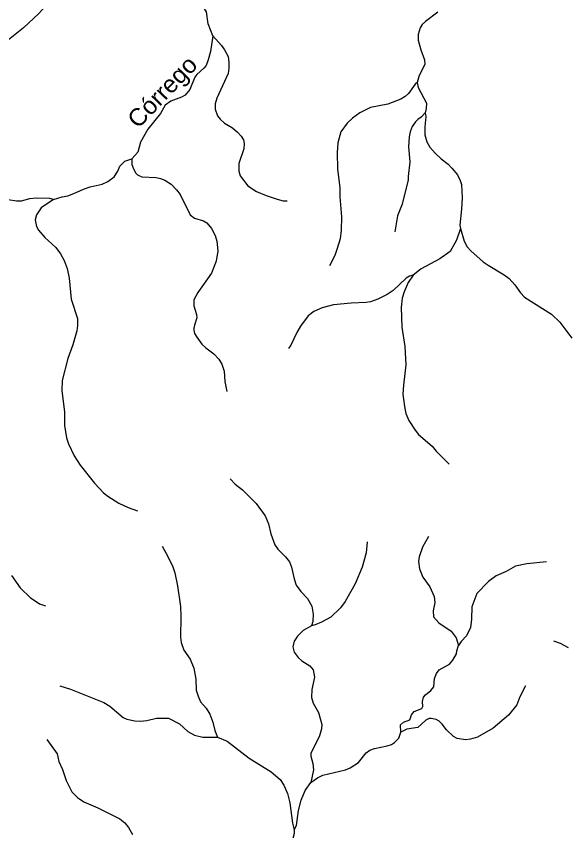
# Model space of a CAD drawing. Extents: x 320.3 to 346.3, y 7455.4 to 7483.3.
# Drawn here: x 330.97 to 333.514, y 7475.68 to 7479.448 of the extents above; entities that cross this region are included whole.
import ezdxf
from ezdxf.enums import TextEntityAlignment as Align

# ---------------------------------------------------------------- set-up
doc = ezdxf.new("R2010")
doc.units = 0
doc.header["$LTSCALE"] = 0.032
doc.layers.add('61', color=7, linetype='Continuous')
doc.layers.add('7', color=7, linetype='Continuous', lineweight=25)

msp = doc.modelspace()

# ---------------------------------------------------------------- linework, layer by layer
at = {"layer": '7'}
for points in [[(331.3345, 7479.939), (331.3321, 7479.921), (331.3062, 7479.8423), (331.267, 7479.7766), (331.2129, 7479.6574), (331.1436, 7479.5398), (331.0749, 7479.4599), (331.0041, 7479.3943), (330.8778, 7479.2962), (330.7232, 7479.1426), (330.6617, 7479.0873), (330.5618, 7479.0211), (330.529, 7479.0038), (330.4669, 7478.9821), (330.4066, 7478.9561)], [(331.8798, 7479.3576), (331.8585, 7479.4129), (331.8506, 7479.468), (331.8371, 7479.4895), (331.8191, 7479.504), (331.8043, 7479.5209), (331.7852, 7479.5696), (331.7806, 7479.589), (331.7786, 7479.6433), (331.7837, 7479.6656), (331.8182, 7479.7511), (331.8217, 7479.7725), (331.8186, 7479.8062)], [(332.9214, 7479.4663), (332.8643, 7479.4231), (332.8492, 7479.4091), (332.8398, 7479.3949), (332.8313, 7479.3626), (332.8313, 7479.3365), (332.8432, 7479.2923), (332.8606, 7479.2457), (332.8611, 7479.2246), (332.8358, 7479.1732), (332.8256, 7479.1406)], [(331.8798, 7479.3576), (331.8691, 7479.2848), (331.8582, 7479.2466), (331.8489, 7479.2196), (331.8376, 7479.2069), (331.8066, 7479.1787), (331.7966, 7479.1657), (331.7739, 7479.1091), (331.7519, 7479.0823), (331.7354, 7479.0742), (331.6855, 7479.0546), (331.6593, 7479.0358), (331.6381, 7478.9985), (331.5791, 7478.925), (331.5444, 7478.8645), (331.5322, 7478.8192), (331.5042, 7478.7888)], [(331.8798, 7479.3576), (331.9205, 7479.3129), (331.9345, 7479.2922), (331.9502, 7479.2613), (331.9544, 7479.2342), (331.9533, 7479.2075), (331.9502, 7479.1822), (331.8983, 7479.069), (331.8911, 7479.0426), (331.8903, 7479.0185), (331.9017, 7478.9878), (331.9135, 7478.9721), (331.9346, 7478.9538), (331.9705, 7478.9319), (331.9946, 7478.912), (332.0114, 7478.8928), (332.0214, 7478.8755), (332.025, 7478.8595), (332.0241, 7478.8348), (332.0004, 7478.7666), (332.0004, 7478.7314), (332.0065, 7478.7099), (332.0419, 7478.6627), (332.0825, 7478.6366), (332.1263, 7478.6178), (332.1785, 7478.601), (332.2058, 7478.594), (332.2248, 7478.5933)], [(332.8256, 7479.1406), (332.8174, 7479.1336), (332.7858, 7479.091), (332.7699, 7479.0763), (332.75, 7479.0638), (332.6906, 7479.0412), (332.6096, 7479.0262), (332.5611, 7479.0008), (332.5267, 7478.9756), (332.5015, 7478.9524), (332.473, 7478.9126), (332.4592, 7478.8619), (332.4556, 7478.8169), (332.4575, 7478.7406), (332.4685, 7478.6561), (332.4686, 7478.6125), (332.4762, 7478.5198), (332.4747, 7478.4581), (332.4695, 7478.4176), (332.4561, 7478.3732), (332.444, 7478.3408), (332.4203, 7478.2932)], [(332.8256, 7479.1406), (332.8306, 7479.118), (332.8688, 7479.0462), (332.8681, 7479.0204), (332.8626, 7479.0009)], [(332.8626, 7479.0009), (332.845, 7478.9807), (332.8291, 7478.9708), (332.8176, 7478.959), (332.8025, 7478.9374), (332.7938, 7478.9134), (332.789, 7478.8893), (332.7863, 7478.8436), (332.7927, 7478.7741), (332.7841, 7478.7067), (332.7847, 7478.691), (332.7564, 7478.5787), (332.735, 7478.5245), (332.7228, 7478.4509)], [(332.8626, 7479.0009), (332.8666, 7478.9819), (332.8612, 7478.9361), (332.8613, 7478.8993), (332.8703, 7478.8668), (332.8852, 7478.842), (332.9087, 7478.8142), (332.937, 7478.7877), (332.9699, 7478.7635), (332.9865, 7478.7454), (333.0119, 7478.7142), (333.0255, 7478.6874), (333.0307, 7478.6688), (333.0341, 7478.6077), (333.0318, 7478.555), (333.023, 7478.4806), (333.0264, 7478.4665)], [(331.1427, 7478.6005), (331.1818, 7478.6124), (331.2084, 7478.617), (331.2372, 7478.6272), (331.2813, 7478.6485), (331.3127, 7478.6588), (331.3672, 7478.671), (331.394, 7478.6826), (331.4226, 7478.7044), (331.4404, 7478.731), (331.45, 7478.7539), (331.4662, 7478.7712), (331.473, 7478.7766), (331.5042, 7478.7888)], [(331.5042, 7478.7888), (331.5053, 7478.7622), (331.5121, 7478.7412), (331.523, 7478.7211), (331.5317, 7478.7134), (331.551, 7478.7053), (331.6173, 7478.7016), (331.6383, 7478.6977), (331.6577, 7478.6901), (331.6872, 7478.6703), (331.7121, 7478.6447), (331.7282, 7478.6226), (331.7754, 7478.5287), (331.7944, 7478.5139), (331.8365, 7478.5007), (331.8526, 7478.4915), (331.8745, 7478.4651), (331.8912, 7478.4332), (331.8981, 7478.4069), (331.9037, 7478.3632), (331.8958, 7478.3155), (331.8736, 7478.2594), (331.8098, 7478.1702), (331.7921, 7478.136), (331.7917, 7478.1086), (331.8045, 7478.0687), (331.8056, 7478.0525), (331.7944, 7478.0184), (331.7914, 7478.0052), (331.7922, 7477.9955), (331.7957, 7477.9808), (331.8056, 7477.9624), (331.8289, 7477.9315), (331.8481, 7477.9139), (331.8844, 7477.8856), (331.9078, 7477.8612), (331.9218, 7477.8387), (331.9322, 7477.8052), (331.9355, 7477.7575), (331.9448, 7477.7123)], [(331.1427, 7478.6005), (331.1254, 7478.6046), (331.0642, 7478.606), (331.0313, 7478.603), (330.992, 7478.5928), (330.9705, 7478.5919), (330.8927, 7478.6045), (330.8653, 7478.6021), (330.829, 7478.5839), (330.81, 7478.5678), (330.7759, 7478.4927)], [(331.1427, 7478.6005), (331.0846, 7478.562), (331.0629, 7478.5296), (331.0574, 7478.5055), (331.0638, 7478.4749), (331.0724, 7478.4579), (331.1019, 7478.4235), (331.1538, 7478.3775), (331.1753, 7478.3494), (331.192, 7478.3177), (331.2055, 7478.2813), (331.2142, 7478.236), (331.2234, 7478.1392), (331.2527, 7478.0495), (331.2536, 7478.017), (331.2501, 7477.9918), (331.2325, 7477.9275), (331.2081, 7477.8644), (331.1826, 7477.7633), (331.1814, 7477.716), (331.1925, 7477.6157), (331.1926, 7477.5547), (331.2031, 7477.4976), (331.2123, 7477.4702), (331.2382, 7477.4141), (331.2656, 7477.3711), (331.3314, 7477.2883), (331.3741, 7477.2433), (331.3943, 7477.2271), (331.4453, 7477.1952), (331.4881, 7477.1755), (331.5313, 7477.1604)], [(333.0264, 7478.4665), (333.0083, 7478.4112), (332.9787, 7478.3597), (332.9313, 7478.3263), (332.8444, 7478.2789), (332.8068, 7478.2505)], [(333.0264, 7478.4665), (333.0431, 7478.408), (333.0576, 7478.3812), (333.0738, 7478.3618), (333.131, 7478.3122), (333.1546, 7478.2969), (333.2293, 7478.2518), (333.2516, 7478.2345), (333.2777, 7478.2045), (333.3036, 7478.1675), (333.3229, 7478.1481), (333.4475, 7478.0699), (333.4869, 7478.0319), (333.5413, 7477.9584)], [(332.8068, 7478.2505), (332.7902, 7478.2453), (332.7753, 7478.2355), (332.7148, 7478.1787), (332.6874, 7478.1606), (332.6438, 7478.1394), (332.6096, 7478.1273), (332.5895, 7478.1237), (332.52, 7478.1207), (332.438, 7478.1125), (332.3865, 7478.0985), (332.3479, 7478.0815), (332.3215, 7478.0617), (332.2854, 7478.0144), (332.2683, 7477.9851), (332.2413, 7477.9261), (332.2304, 7477.9102)], [(332.8068, 7478.2505), (332.7837, 7478.2161), (332.7655, 7478.1733), (332.7569, 7478.1433), (332.7519, 7478.1006), (332.755, 7478.0096), (332.769, 7477.9194), (332.774, 7477.8348), (332.7619, 7477.741), (332.7598, 7477.6999), (332.7668, 7477.6423), (332.7742, 7477.6102), (332.7875, 7477.5774), (332.8165, 7477.5325), (332.8328, 7477.513), (332.8948, 7477.4592), (332.9143, 7477.4353), (332.9746, 7477.376)], [(331.9609, 7477.3085), (331.9828, 7477.2833), (332.0172, 7477.2567), (332.0807, 7477.1929), (332.1216, 7477.1369), (332.1379, 7477.1001), (332.1484, 7477.0531), (332.1676, 7477.0019), (332.1811, 7476.9824), (332.2158, 7476.9471), (332.2346, 7476.9231), (332.2446, 7476.899), (332.2564, 7476.8451), (332.2663, 7476.8159), (332.2874, 7476.7859), (332.3186, 7476.7541), (332.3377, 7476.7182), (332.3443, 7476.6817), (332.3425, 7476.6479), (332.3367, 7476.6277)], [(332.8781, 7477.0413), (332.8511, 7476.991), (332.8346, 7476.9471), (332.8322, 7476.9259), (332.8372, 7476.8912), (332.8517, 7476.8533), (332.8839, 7476.8086), (332.904, 7476.7639), (332.9077, 7476.7359), (332.8999, 7476.697), (332.9016, 7476.6693), (332.9261, 7476.6418), (332.984, 7476.6027), (333.006, 7476.5729), (333.0176, 7476.5365)], [(332.5941, 7477.0156), (332.5893, 7476.9649), (332.5718, 7476.8998), (332.5389, 7476.8226), (332.4932, 7476.7399), (332.471, 7476.7106), (332.4266, 7476.6682), (332.3826, 7476.6442), (332.3541, 7476.6316), (332.3367, 7476.6277)], [(331.6447, 7476.9963), (331.6707, 7476.9516), (331.6945, 7476.9008), (331.7036, 7476.8734), (331.7165, 7476.8126), (331.7299, 7476.7177), (331.7322, 7476.671), (331.73, 7476.5756), (331.7335, 7476.5501), (331.7463, 7476.5159), (331.7755, 7476.4732), (331.7926, 7476.4319), (331.8006, 7476.3807), (331.803, 7476.3302), (331.8113, 7476.3018), (331.8228, 7476.276), (331.8489, 7476.2462), (331.8657, 7476.2184), (331.8798, 7476.182), (331.8895, 7476.1433), (331.9021, 7476.113)], [(333.4252, 7476.9231), (333.3331, 7476.9146), (333.2811, 7476.9039), (333.2376, 7476.8794), (333.1915, 7476.8584), (333.1561, 7476.8331), (333.1027, 7476.778), (333.0797, 7476.7158), (333.0781, 7476.6585), (333.073, 7476.6206), (333.0545, 7476.5814), (333.0296, 7476.5545), (333.0176, 7476.5365)], [(330.9478, 7476.8605), (330.988, 7476.8039), (331.0366, 7476.7577), (331.057, 7476.7429), (331.0779, 7476.7299), (331.1049, 7476.7195)], [(332.3367, 7476.6277), (332.298, 7476.6055), (332.2723, 7476.58), (332.2572, 7476.5575), (332.2505, 7476.5313), (332.2566, 7476.5063), (332.2747, 7476.4817), (332.2924, 7476.4662), (332.3296, 7476.4433), (332.3449, 7476.4249), (332.3502, 7476.3908), (332.3385, 7476.3338), (332.337, 7476.2964), (332.3437, 7476.2703), (332.3698, 7476.2261), (332.3839, 7476.1714), (332.383, 7476.1509), (332.3741, 7476.1189), (332.334, 7476.0366), (332.3338, 7476.0248), (332.3433, 7475.9908), (332.3463, 7475.9608), (332.3331, 7475.9029)], [(333.5272, 7476.5255), (333.4888, 7476.5464), (333.4589, 7476.557)], [(332.7497, 7476.1352), (332.7482, 7476.169), (332.7621, 7476.1817), (332.7919, 7476.1923), (332.7995, 7476.2165), (332.8114, 7476.2314), (332.8472, 7476.2457), (332.8521, 7476.2553), (332.8502, 7476.2778), (332.8558, 7476.2971), (332.8644, 7476.3085), (332.8891, 7476.3284), (332.9028, 7476.3459), (332.9065, 7476.3833), (332.9153, 7476.407), (332.9282, 7476.4244), (332.9755, 7476.4511), (332.9918, 7476.4694), (333.0085, 7476.498), (333.0096, 7476.5125), (333.0176, 7476.5365)], [(331.1709, 7476.3503), (331.2216, 7476.3352), (331.3747, 7476.2734), (331.4038, 7476.2563), (331.4648, 7476.2036), (331.4811, 7476.1953), (331.5186, 7476.1875), (331.5437, 7476.1864), (331.5749, 7476.1897), (331.6189, 7476.2006), (331.6741, 7476.2004), (331.7251, 7476.1743), (331.7642, 7476.1393), (331.7957, 7476.1213), (331.8339, 7476.1132), (331.9021, 7476.113)], [(333.3278, 7476.3495), (333.3019, 7476.2994), (333.2877, 7476.2623), (333.249, 7476.2138), (333.1776, 7476.154), (333.1045, 7476.1124), (333.0735, 7476.1039), (333.0494, 7476.101), (333.0108, 7476.1068), (332.9935, 7476.1161), (332.961, 7476.1464), (332.9411, 7476.1732), (332.9276, 7476.1861), (332.914, 7476.1939), (332.8911, 7476.1989), (332.8808, 7476.1987), (332.8666, 7476.192), (332.8287, 7476.1576), (332.7775, 7476.1497), (332.7497, 7476.1352)], [(332.3331, 7475.9029), (332.3651, 7475.9247), (332.3886, 7475.9365), (332.4935, 7475.9618), (332.5152, 7475.9703), (332.5547, 7475.9952), (332.5891, 7476.0395), (332.6072, 7476.0529), (332.6278, 7476.0607), (332.6871, 7476.0722), (332.7065, 7476.0792), (332.7206, 7476.0884), (332.7414, 7476.1082), (332.7497, 7476.1352)], [(331.1113, 7476.1017), (331.1599, 7476.035), (331.1671, 7475.9997), (331.1847, 7475.9631), (331.2005, 7475.9119), (331.2274, 7475.8592), (331.2538, 7475.8329), (331.2827, 7475.8133), (331.3477, 7475.7853), (331.4487, 7475.7356), (331.4724, 7475.7159), (331.4901, 7475.6943), (331.5073, 7475.6623)], [(331.9021, 7476.113), (331.9465, 7476.0935), (332.048, 7476.0161), (332.1502, 7475.9524), (332.1916, 7475.9163), (332.2092, 7475.8913), (332.226, 7475.8524), (332.2359, 7475.8095), (332.2489, 7475.7154), (332.2562, 7475.6844)], [(332.2562, 7475.6844), (332.2667, 7475.7037), (332.2758, 7475.7738), (332.2896, 7475.8209), (332.3076, 7475.8664), (332.3331, 7475.9029)], [(332.2562, 7475.6844), (332.2559, 7475.6666), (332.2476, 7475.6313)]]:
    msp.add_lwpolyline(points, dxfattribs=at)

# ---------------------------------------------------------------- texts
at = {"layer": '61', "width": 1.05}
msp.add_text('Córrego', height=0.08, rotation=46.238, dxfattribs=at).set_placement((331.6746, 7479.0707), align=Align.CENTER)

doc.saveas('drawing.dxf')
